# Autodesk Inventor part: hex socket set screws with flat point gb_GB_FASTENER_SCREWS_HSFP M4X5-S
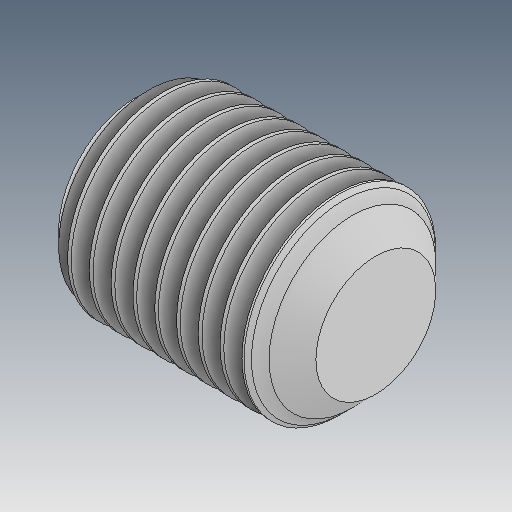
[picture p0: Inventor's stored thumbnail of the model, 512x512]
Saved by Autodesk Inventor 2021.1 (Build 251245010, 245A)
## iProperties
Created: 2019-04
Part Number: hex socket set screws with flat point gb_GB_FASTENER_SCREWS_HSFP M4X5-S
Material: Ogólny
Document SubType Name: Modeling
Designer: user
Density: 1 g/cm^3
Appearance: Domyślna
Author: user
Revision Number: ÈÎºÎ
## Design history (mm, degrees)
feature "LPattern10"
node "Bryła1"
